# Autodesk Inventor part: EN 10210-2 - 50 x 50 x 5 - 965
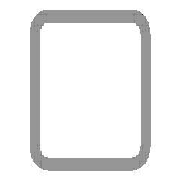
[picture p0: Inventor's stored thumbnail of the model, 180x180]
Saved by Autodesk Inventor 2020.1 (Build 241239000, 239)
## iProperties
_CCFamilyMember: 16
_CCFamilyDisplayName: DIN EN 10210-2 (USAS B17.1 quadratisch) - Rohrleitung — In Klammern angegebene Größen wurden aufgehoben
_FrameMemberDoc: Frame Member File
_Version: 15.0.0
_GetPNFromCC: 1
IsCustomPart: 1
Created: 2019-10
Part Number: EN 10210-2 - 50 x 50 x 5 - 965
Material: Stahl, weich
Description: Rohrleitung
Document SubType Name: Modeling
Standard: DIN
Designer: lutzd
Standard Revision: 2006-07
Standards Organization: DIN
Language: de-DE
Size Designation: 50 x 50 x 5
Categories: <MemberInstance><Categories><Category DisplayName="Profile" InternalName="089c4875-fa83-4c05-b084-43b9cc11f5ed" Mnemonic="GRDR"><CategoryParameter DisplayName="
Stock Number: 50 x 50 x 5
Mass: 6614.52 g
Surface Area: 3284.37 cm^2
Volume: 842.614 cm^3
Density: 7.85 g/cm^3
Appearance: Halbpoliert
G_L: 965,000 mm
G_W: 50,000 mm
G_H: 50,000 mm
Dimensions: 50x50x965 mm
Mass: 6,615 kg
DocNumber: ADSK-014101
Folder: .
+12AA4EFD-519B-4E13-AA62-1FD2C4FA85C6+SCHNITTDETAIL1: Schnittwinkel 90,00 grd
Title: Profil-Bauteil
Author: lutzd
Revision Number: -
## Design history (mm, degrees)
node "Startebene"
node "Endebene"
sketch "Skizze"
  geometry: L1 (-25, -17.5)-(-25, 17.5); L2 (-17.5, 25)-(17.5, 25); L3 (25, 17.5)-(25, -17.5); L4 (17.5, -25)-(-17.5, -25); L5 (-15, 20)-(15, 20); L6 (20, 15)-(20, -15); L7 (15, -20)-(-15, -20); L8 (-20, -15)-(-20, 15); L9 (0, 37.175)-(0, -37.175) reference; L10 (-37.175, 0)-(37.175, 0) reference; A1 r 7.5 centre (-17.5, -17.5) between (-25, -17.5) and (-17.5, -25); A2 r 7.5 centre (-17.5, 17.5) between (-17.5, 25) and (-25, 17.5); A3 r 7.5 centre (17.5, 17.5) between (25, 17.5) and (17.5, 25); A4 r 7.5 centre (17.5, -17.5) between (17.5, -25) and (25, -17.5); A5 r 5 centre (-15, -15) between (-20, -15) and (-15, -20); A6 r 5 centre (-15, 15) between (-15, 20) and (-20, 15); A7 r 5 centre (15, 15) between (20, 15) and (15, 20); A8 r 5 centre (15, -15) between (15, -20) and (20, -15)
  constraints: 16 end point, 16 point on circle, 16 tangent, 8 centre point, 6 equal radius, 4 parallel, 2 perpendicular, 2 other
  dimensions: "d7" = 7.5 radius of A1 (= G_IR); "d10" = 50 distance between parallel lines of L2 L4 (= G_H); "d11" = 50 distance between parallel lines of L1 L3 (= G_W); "d12" = 5 distance between parallel lines of L3 L6 (= G_T); "d15" = 25 distance between parallel lines of L2 L10 (= 0.5 x d10); "d16" = 25 distance between parallel lines of L9 L3 (= 0.5 x d11); "d19" = 5 radius of A5 (= G_T); "d20" = 5 distance between parallel lines of L4 L7 (= G_T)
extrude "Körper" new body sketch "Skizze" stored distance "d3" = 965 (= G_L); taper "d4" = 0 deg
node "Driven Length"
  sketch "Sketch3"
    geometry: L1 (0, 0)-(10, 0) reference
    constraints: 2 end point, 1 horizontal
  workplane "Work Plane3"
  sketch "Sketch4"
    geometry: L1 (-2, 35)-(12, 35) reference; L2 (-2, 1000)-(12, 1000) reference
    dimensions: "d18" = 965 distance between parallel lines of L1 L2 (derived)
workplane "Arbeitsebene4"
feature "Trennen1"
body "Solid1"
other parameters: "G_W" = 50 [user parameter; used in 1 equation term], "G_H" = 50 [user parameter; used in 1 equation term], "G_T" = 5 [user parameter; used in 3 equation terms], "G_IR" = 7.5 [user parameter; used in 1 equation term], "G_L" = 965 (= d18) [user parameter; used in 1 equation term], "G_OFFSET_START" = -35 [user parameter; used in 1 equation term], "d13" = 35 (= -G_OFFSET_START), "d17" = 90 deg
